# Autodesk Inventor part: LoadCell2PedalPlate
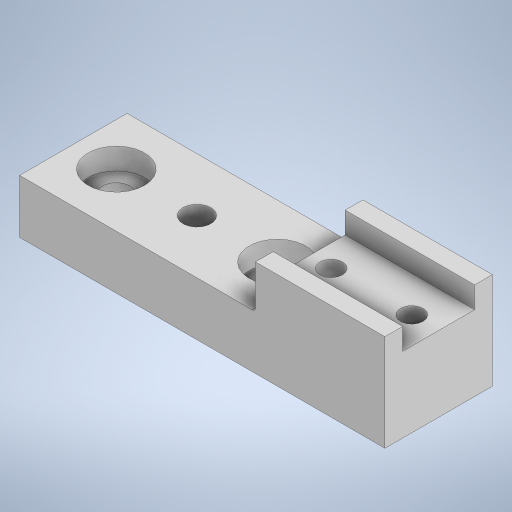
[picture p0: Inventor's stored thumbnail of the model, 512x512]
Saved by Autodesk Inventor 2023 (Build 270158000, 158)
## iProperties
Created: 2023-06
Part Number: LoadCell2PedalPlate
Material: Generic
Document SubType Name: Modeling
Designer: Admin
Density: 1 g/cm^3
Appearance: Default
Author: Admin
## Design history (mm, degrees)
sketch "Sketch1"
  geometry: L1 (0, 0)-(68, 0); L2 (68, 0)-(68, -20); L3 (68, -20)-(0, -20); L4 (0, -20)-(0, 0); L5 (60, -10)-(30, -10); L6 (30, -10)-(0, -10); C1 r 2.6 at (60, -10); C2 r 2.6 at (30, -10); C3 r 2.6 at (45, -10); C4 r 2.1 at (5, -10); C5 r 2.1 at (20, -10)
  constraints: 12 end point, 5 centre point, 3 equal radius, 3 parallel, 2 horizontal, 2 midpoint, 2 point on line, 1 perpendicular
  dimensions: "d0" = 20 distance between parallel lines of L3 L1; "d2" = 30 distance of L5.start L5.end; "d3" = 8 distance from line of L5.start L2; "d5" = 5.2 diameter of C1; "d10" = 60 distance from line of L4 L5.start; "d14" = 4.2 diameter of C4; "d16" = 5 distance from line of L4 C4.centre; "d17" = 15 distance of C5.centre C4.centre
extrude "Extrusion1" new body sketch "Sketch1" distance "d6" = 10; taper "d7" = 0 deg
sketch "Sketch2"
  geometry: C1 r 2.6 at (-60, 10) reference; C2 r 5.25 at (-60, 10); C3 r 2.6 at (-30, 10) reference; C4 r 5.25 at (-30, 10); 1 further point
  constraints: 2 centre point, 2 coincident, 1 equal radius
  dimensions: "d18" = 10.5 diameter of C2
extrude "Extrusion2" cut sketch "Sketch2" distance "d19" = 4; taper "d20" = 0 deg
chamfer "Chamfer2" distance "d21" = 2; stored, may be unused: second distance "d22" = 2, angle "d23" = 45 deg
sketch "Sketch3"
  geometry: L1 (0, 20)-(-68, 20) reference; L2 (0, 0)-(0, 20) reference; L3 (-24.1, 20)-(0, 20); L4 (0, 20)-(0, 0); L5 (0, 0)-(-24.1, 0); L6 (-24.1, 0)-(-24.1, 20); C1 r 2.1 at (-5, 10); C2 r 2.1 at (-5, 10) reference; C3 r 4.1 at (-20, 10) reference; C4 r 2.1 at (-20, 10); C5 r 2.1 at (-20, 10) reference; 1 further point
  constraints: 8 end point, 4 concentric, 2 centre point, 2 parallel, 1 horizontal, 1 perpendicular, 1 point on line, 1 tangent
extrude "Extrusion3" join sketch "Sketch3" distance "d24" = 4; taper "d25" = 0 deg
sketch "Sketch4"
  geometry: L1 (-24.1, 20)-(-24.1, 0) reference; L2 (-24.1, 20)-(0, 20); L3 (0, 20)-(0, 16.7); L4 (0, 16.7)-(-24.1, 16.7); L5 (-24.1, 16.7)-(-24.1, 20); L6 (0, 0)-(-24.1, 0); L7 (-24.1, 0)-(-24.1, 3.3); L8 (-24.1, 3.3)-(0, 3.3); L9 (0, 3.3)-(0, 0); 3 further points
  constraints: 16 end point, 4 parallel, 2 collinear, 2 horizontal, 2 perpendicular, 1 point on line
  dimensions: "d26" = 13.4 distance between parallel lines of L8 L4
extrude "Extrusion4" join sketch "Sketch4" distance "d27" = 4; taper "d28" = 0 deg
fillet "Fillet1" dims "d29" = 0.6
body "Solid1"
